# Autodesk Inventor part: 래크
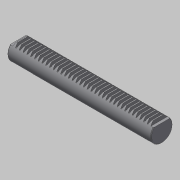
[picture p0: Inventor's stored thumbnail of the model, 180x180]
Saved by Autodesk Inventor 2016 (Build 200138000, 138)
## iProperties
Created: 2019-06
Part Number: 래크
Material: 스테인리스강
Document SubType Name: Modeling
Designer: mduedu
Density: 1 g/cm^3
Appearance: 기본값
Author: mduedu
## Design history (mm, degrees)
sketch "스케치1"
  geometry: L1 (0, 0)-(240, 0); L2 (240, 0)-(240, 34); L3 (240, 34)-(0, 34); L4 (0, 34)-(0, 0)
  constraints: 8 end point, 2 parallel, 1 horizontal, 1 perpendicular
  dimensions: "d0" = 240 distance of L1.start L1.end; "d1" = 34 distance of L1.end L2.end
extrude "돌출1" new body sketch "스케치1" stored distance "d2" = 36; taper "d3" = 0 deg
sketch "스케치2"
  geometry: L1 (0, 0)-(240, 0) reference; L2 (240, 0)-(240, 34) reference; L3 (240, 34)-(0, 34) reference; L4 (0, 34)-(0, 0) reference; L5 (9.44, 29.5)-(10.76, 29.5); L6 (12.398, 34)-(7.802, 34); L7 (10.1, 34)-(10.1, 29.5); L8 (7.802, 34)-(9.44, 29.5); L9 (12.398, 34)-(10.76, 29.5); L10 (8.53, 32)-(11.67, 32); 1 further point
  constraints: 12 end point, 2 midpoint, 2 point on line, 1 collinear, 1 horizontal, 1 parallel, 1 perpendicular, 1 symmetric about line
  dimensions: "d4" = 20 deg angle of L9 L7; "d5" = 2 distance between parallel lines of L10 L6; "d7" = 4.5 distance between parallel lines of L5 L6 (= 2.25 x d5); "d8" = 3.14 distance of L10.start L10.end; "d9" = 10.1 distance between parallel lines of L4 L7
extrude "돌출2" cut sketch "스케치2" stored distance "d10" = 36; taper "d11" = 0 deg
sketch "스케치3"
  geometry: L1 (235.52, 29.5)-(233.882, 34) reference; L2 (233.882, 34)-(232.198, 34) reference; L3 (232.198, 34)-(230.56, 29.5) reference; L4 (230.56, 29.5)-(229.24, 29.5) reference; L5 (229.24, 29.5)-(227.602, 34) reference; L6 (227.602, 34)-(225.918, 34) reference; L7 (225.918, 34)-(224.28, 29.5) reference; L8 (224.28, 29.5)-(222.96, 29.5) reference; L9 (222.96, 29.5)-(221.322, 34) reference; L10 (221.322, 34)-(219.638, 34) reference; L11 (219.638, 34)-(218, 29.5) reference; L12 (218, 29.5)-(216.68, 29.5) reference; L13 (216.68, 29.5)-(215.042, 34) reference; L14 (215.042, 34)-(213.358, 34) reference; L15 (213.358, 34)-(211.72, 29.5) reference; L16 (211.72, 29.5)-(210.4, 29.5) reference; L17 (210.4, 29.5)-(208.762, 34) reference; L18 (208.762, 34)-(207.078, 34) reference; L19 (207.078, 34)-(205.44, 29.5) reference; L20 (205.44, 29.5)-(204.12, 29.5) reference; L21 (204.12, 29.5)-(202.482, 34) reference; L22 (202.482, 34)-(200.798, 34) reference; L23 (200.798, 34)-(199.16, 29.5) reference; L24 (199.16, 29.5)-(197.84, 29.5) reference; L25 (197.84, 29.5)-(196.202, 34) reference; L26 (196.202, 34)-(194.518, 34) reference; L27 (194.518, 34)-(192.88, 29.5) reference; L28 (192.88, 29.5)-(191.56, 29.5) reference; L29 (191.56, 29.5)-(189.922, 34) reference; L30 (189.922, 34)-(188.238, 34) reference; L31 (188.238, 34)-(186.6, 29.5) reference; L32 (186.6, 29.5)-(185.28, 29.5) reference; L33 (185.28, 29.5)-(183.642, 34) reference; L34 (183.642, 34)-(181.958, 34) reference; L35 (181.958, 34)-(180.32, 29.5) reference; L36 (180.32, 29.5)-(179, 29.5) reference; L37 (179, 29.5)-(177.362, 34) reference; L38 (177.362, 34)-(175.678, 34) reference; L39 (175.678, 34)-(174.04, 29.5) reference; L40 (174.04, 29.5)-(172.72, 29.5) reference; L41 (172.72, 29.5)-(171.082, 34) reference; L42 (171.082, 34)-(169.398, 34) reference; L43 (169.398, 34)-(167.76, 29.5) reference; L44 (167.76, 29.5)-(166.44, 29.5) reference; L45 (166.44, 29.5)-(164.802, 34) reference; L46 (164.802, 34)-(163.118, 34) reference; L47 (163.118, 34)-(161.48, 29.5) reference; L48 (161.48, 29.5)-(160.16, 29.5) reference; L49 (160.16, 29.5)-(158.522, 34) reference; L50 (158.522, 34)-(156.838, 34) reference; L51 (156.838, 34)-(155.2, 29.5) reference; L52 (155.2, 29.5)-(153.88, 29.5) reference; L53 (153.88, 29.5)-(152.242, 34) reference; L54 (152.242, 34)-(150.558, 34) reference; L55 (150.558, 34)-(148.92, 29.5) reference; L56 (148.92, 29.5)-(147.6, 29.5) reference; L57 (147.6, 29.5)-(145.962, 34) reference; L58 (145.962, 34)-(144.278, 34) reference; L59 (144.278, 34)-(142.64, 29.5) reference; L60 (142.64, 29.5)-(141.32, 29.5) reference; L61 (141.32, 29.5)-(139.682, 34) reference; L62 (139.682, 34)-(137.998, 34) reference; L63 (137.998, 34)-(136.36, 29.5) reference; L64 (136.36, 29.5)-(135.04, 29.5) reference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; 1 further point
  constraints: 16 end point, 4 parallel, 2 horizontal, 2 perpendicular
extrude "돌출3" cut sketch "스케치3" stored distance "d18" = 36; taper "d19" = 0 deg
sketch "스케치4"
  geometry: L1 (4.48, 29.5)-(0, 29.5) reference; L2 (0, 29.5)-(0, 0) reference; L3 (0, 0)-(240, 0) reference; L4 (240, 0)-(240, 29.5) reference; L5 (240, 29.5)-(235.52, 29.5) reference; L6 (235.52, 29.5)-(233.882, 34) reference; L7 (233.882, 34)-(232.198, 34) reference; L8 (232.198, 34)-(230.56, 29.5) reference; L9 (230.56, 29.5)-(229.24, 29.5) reference; L10 (229.24, 29.5)-(227.602, 34) reference; L11 (227.602, 34)-(225.918, 34) reference; L12 (225.918, 34)-(224.28, 29.5) reference; L13 (224.28, 29.5)-(222.96, 29.5) reference; L14 (222.96, 29.5)-(221.322, 34) reference; L15 (221.322, 34)-(219.638, 34) reference; L16 (219.638, 34)-(218, 29.5) reference; L17 (218, 29.5)-(216.68, 29.5) reference; L18 (216.68, 29.5)-(215.042, 34) reference; L19 (215.042, 34)-(213.358, 34) reference; L20 (213.358, 34)-(211.72, 29.5) reference; L21 (211.72, 29.5)-(210.4, 29.5) reference; L22 (210.4, 29.5)-(208.762, 34) reference; L23 (208.762, 34)-(207.078, 34) reference; L24 (207.078, 34)-(205.44, 29.5) reference; L25 (205.44, 29.5)-(204.12, 29.5) reference; L26 (204.12, 29.5)-(202.482, 34) reference; L27 (202.482, 34)-(200.798, 34) reference; L28 (200.798, 34)-(199.16, 29.5) reference; L29 (199.16, 29.5)-(197.84, 29.5) reference; L30 (197.84, 29.5)-(196.202, 34) reference; L31 (196.202, 34)-(194.518, 34) reference; L32 (194.518, 34)-(192.88, 29.5) reference; L33 (192.88, 29.5)-(191.56, 29.5) reference; L34 (191.56, 29.5)-(189.922, 34) reference; L35 (189.922, 34)-(188.238, 34) reference; L36 (188.238, 34)-(186.6, 29.5) reference; L37 (186.6, 29.5)-(185.28, 29.5) reference; L38 (185.28, 29.5)-(183.642, 34) reference; L39 (183.642, 34)-(181.958, 34) reference; L40 (181.958, 34)-(180.32, 29.5) reference; L41 (180.32, 29.5)-(179, 29.5) reference; L42 (179, 29.5)-(177.362, 34) reference; L43 (177.362, 34)-(175.678, 34) reference; L44 (175.678, 34)-(174.04, 29.5) reference; L45 (174.04, 29.5)-(172.72, 29.5) reference; L46 (172.72, 29.5)-(171.082, 34) reference; L47 (171.082, 34)-(169.398, 34) reference; L48 (169.398, 34)-(167.76, 29.5) reference; L49 (167.76, 29.5)-(166.44, 29.5) reference; L50 (166.44, 29.5)-(164.802, 34) reference; L51 (164.802, 34)-(163.118, 34) reference; L52 (163.118, 34)-(161.48, 29.5) reference; L53 (161.48, 29.5)-(160.16, 29.5) reference; L54 (160.16, 29.5)-(158.522, 34) reference; L55 (158.522, 34)-(156.838, 34) reference; L56 (156.838, 34)-(155.2, 29.5) reference; L57 (155.2, 29.5)-(153.88, 29.5) reference; L58 (153.88, 29.5)-(152.242, 34) reference; L59 (152.242, 34)-(150.558, 34) reference; L60 (150.558, 34)-(148.92, 29.5) reference; L61 (148.92, 29.5)-(147.6, 29.5) reference; L62 (147.6, 29.5)-(145.962, 34) reference; L63 (145.962, 34)-(144.278, 34) reference; L64 (144.278, 34)-(142.64, 29.5) reference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; 1 further point
  constraints: 8 end point, 2 parallel, 1 horizontal, 1 perpendicular, 1 point on line
  dimensions: "d20" = 36 distance between parallel lines of L156 L2; "d21" = 10 distance between parallel lines of L4 L154; "d22" = 194 distance between parallel lines of L154 L156 (derived); "d23" = 4 distance between parallel lines of L3 L155
extrude "돌출4" cut sketch "스케치4" stored distance "d24" = 36; taper "d25" = 0 deg
sketch "스케치5"
  geometry: L1 (36, 0)-(0, 0) reference; C1 r 18 at (18, 18); 2 further points
  constraints: 1 centre point, 1 midpoint, 1 tangent, 1 vertical alignment
  dimensions: "d26" = 36 diameter of C1
extrude "돌출5" sketch "스케치5" stored distance "d27" = 36; taper "d28" = 0 deg
chamfer "모따기1" distance "d29" = 1; stored, may be unused: second distance "d30" = 2, angle "d31" = 45 deg
node "솔리드1"
pattern_linear "직사각형 패턴1" dims "d14" = 6.28, "d17" = 6.28
node "투영된 루프1"
node "투영된 루프2"
node "투영된 루프3"
